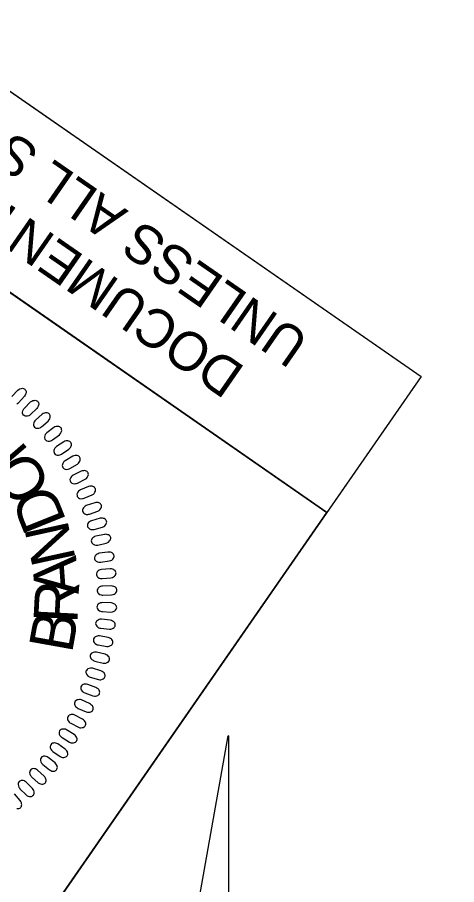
# Model space of a CAD drawing. Extents: x 478372 to 480379, y 492840 to 494699.
# Drawn here: x 478604.8 to 478667.1, y 493764.6 to 493887.7 of the extents above; entities that cross this region are included whole.
import ezdxf

# ---------------------------------------------------------------- set-up
doc = ezdxf.new("R2010")
doc.units = 0
for name, color, linetype in [('Prop North Arrow NAD83 for Plan Sheets CELL', 7, 'Continuous'), ('Sheet Clip Boundary CELL', 7, 'Continuous'), ('Sheet PE Seal Cell', 7, 'Continuous'), ('Sheet Plan CELL', 7, 'Continuous'), ('Sheet Sticker Exception Certification CELL', 7, 'Continuous')]:
    doc.layers.add(name, color=color, linetype=linetype)

msp = doc.modelspace()

# ---------------------------------------------------------------- linework, layer by layer
at = {"layer": 'Prop North Arrow NAD83 for Plan Sheets CELL'}
for p, q in [((478626.5, 493739.35), (478634.7, 493785.7)), ((478634.75, 493785.7), (478634.7, 493785.7)), ((478634.75, 493785.7), (478634.7, 493785.7)), ((478634.75, 493785.7), (478634.75, 493737.9))]:
    msp.add_line(p, q, dxfattribs=at)
at = {"layer": 'Sheet Clip Boundary CELL'}
msp.add_lwpolyline([(479740.65, 493110.71), (479819.09, 493331.13), (479938.9, 493670.6), (480035.01, 493951.06), (479137.46, 494573.68), (479091.85, 494507.93), (479078.63, 494420.53), (478968.98, 494336.48), (478682.91, 494117.93), (478570.32, 494055.33), (478497.76, 493950.74), (478662.13, 493836.73), (478563.21, 493694.11), (479631.38, 492953.18)], close=True, dxfattribs=at)
at = {"layer": 'Sheet PE Seal Cell'}
for points in [[(478604.04, 493833.87), (478604.87, 493834.78), (478605.04, 493834.92), (478605.17, 493834.99), (478605.37, 493835.04), (478605.51, 493835.06), (478605.65, 493835.04), (478605.76, 493835), (478605.85, 493834.94), (478605.92, 493834.85), (478605.99, 493834.75), (478606.03, 493834.64), (478606.04, 493834.49), (478606.03, 493834.39), (478605.98, 493834.24), (478605.91, 493834.06), (478605.82, 493833.93), (478604.98, 493832.99), (478604.85, 493832.88), (478604.72, 493832.81)], [(478604.74, 493775.43), (478604.88, 493775.41), (478605.02, 493775.42), (478605.13, 493775.46), (478605.23, 493775.52), (478605.3, 493775.61), (478605.37, 493775.71), (478605.41, 493775.82), (478605.42, 493775.97), (478605.41, 493776.07), (478605.37, 493776.22), (478605.3, 493776.4), (478605.21, 493776.53), (478604.39, 493777.49)]]:
    msp.add_lwpolyline(points, dxfattribs=at)
for points in [[(478605.8, 493832.25), (478606.68, 493833.11), (478606.86, 493833.24), (478607, 493833.3), (478607.2, 493833.34), (478607.34, 493833.35), (478607.48, 493833.32), (478607.58, 493833.28), (478607.67, 493833.21), (478607.74, 493833.12), (478607.8, 493833.01), (478607.83, 493832.89), (478607.83, 493832.75), (478607.82, 493832.65), (478607.76, 493832.5), (478607.67, 493832.33), (478607.57, 493832.2), (478606.68, 493831.32), (478606.54, 493831.21), (478606.41, 493831.15), (478606.24, 493831.1), (478606.06, 493831.08), (478605.93, 493831.1), (478605.78, 493831.17), (478605.66, 493831.26), (478605.59, 493831.39), (478605.55, 493831.5), (478605.53, 493831.66), (478605.57, 493831.87), (478605.65, 493832.04), (478605.72, 493832.15)], [(478608.25, 493829.6), (478609.18, 493830.4), (478609.32, 493830.57), (478609.39, 493830.7), (478609.44, 493830.9), (478609.46, 493831.05), (478609.45, 493831.18), (478609.41, 493831.29), (478609.35, 493831.39), (478609.27, 493831.46), (478609.16, 493831.53), (478609.05, 493831.57), (478608.91, 493831.58), (478608.81, 493831.58), (478608.65, 493831.53), (478608.48, 493831.46), (478608.34, 493831.37), (478607.38, 493830.55), (478607.27, 493830.43), (478607.2, 493830.3), (478607.13, 493830.13), (478607.1, 493829.95), (478607.1, 493829.83), (478607.16, 493829.67), (478607.24, 493829.54), (478607.37, 493829.45), (478607.48, 493829.41), (478607.64, 493829.38), (478607.84, 493829.4), (478608.02, 493829.46), (478608.14, 493829.53)], [(478609.78, 493827.72), (478610.76, 493828.46), (478610.91, 493828.62), (478610.99, 493828.75), (478611.06, 493828.94), (478611.09, 493829.08), (478611.08, 493829.22), (478611.05, 493829.33), (478611, 493829.43), (478610.91, 493829.51), (478610.82, 493829.58), (478610.71, 493829.63), (478610.56, 493829.65), (478610.46, 493829.65), (478610.3, 493829.62), (478610.13, 493829.56), (478609.98, 493829.48), (478608.98, 493828.72), (478608.86, 493828.6), (478608.77, 493828.48), (478608.7, 493828.31), (478608.66, 493828.14), (478608.65, 493828.01), (478608.7, 493827.85), (478608.78, 493827.72), (478608.9, 493827.63), (478609, 493827.58), (478609.16, 493827.53), (478609.36, 493827.54), (478609.55, 493827.6), (478609.67, 493827.65)], [(478611.08, 493825.72), (478612.1, 493826.4), (478612.27, 493826.55), (478612.35, 493826.67), (478612.43, 493826.86), (478612.47, 493827), (478612.47, 493827.14), (478612.45, 493827.25), (478612.4, 493827.35), (478612.33, 493827.43), (478612.23, 493827.52), (478612.13, 493827.57), (478611.98, 493827.6), (478611.89, 493827.61), (478611.72, 493827.58), (478611.54, 493827.53), (478611.4, 493827.46), (478610.35, 493826.77), (478610.22, 493826.66), (478610.13, 493826.54), (478610.04, 493826.38), (478609.99, 493826.21), (478609.98, 493826.09), (478610.01, 493825.92), (478610.08, 493825.79), (478610.19, 493825.68), (478610.29, 493825.62), (478610.45, 493825.57), (478610.65, 493825.57), (478610.84, 493825.61), (478610.97, 493825.66)], [(478612.26, 493823.68), (478613.32, 493824.29), (478613.49, 493824.43), (478613.58, 493824.55), (478613.67, 493824.73), (478613.72, 493824.87), (478613.73, 493825.01), (478613.72, 493825.12), (478613.68, 493825.22), (478613.6, 493825.31), (478613.52, 493825.4), (478613.41, 493825.46), (478613.27, 493825.5), (478613.18, 493825.51), (478613.01, 493825.5), (478612.83, 493825.46), (478612.68, 493825.4), (478611.59, 493824.77), (478611.45, 493824.67), (478611.35, 493824.56), (478611.26, 493824.4), (478611.19, 493824.24), (478611.17, 493824.11), (478611.2, 493823.95), (478611.26, 493823.81), (478611.37, 493823.7), (478611.46, 493823.63), (478611.61, 493823.57), (478611.82, 493823.55), (478612.01, 493823.59), (478612.14, 493823.62)], [(478613.32, 493821.59), (478614.42, 493822.14), (478614.6, 493822.27), (478614.7, 493822.38), (478614.8, 493822.56), (478614.85, 493822.69), (478614.88, 493822.83), (478614.87, 493822.94), (478614.83, 493823.05), (478614.76, 493823.14), (478614.69, 493823.23), (478614.59, 493823.3), (478614.45, 493823.35), (478614.35, 493823.37), (478614.19, 493823.36), (478614, 493823.34), (478613.85, 493823.28), (478612.72, 493822.73), (478612.58, 493822.64), (478612.47, 493822.53), (478612.37, 493822.38), (478612.29, 493822.22), (478612.26, 493822.1), (478612.28, 493821.93), (478612.33, 493821.79), (478612.43, 493821.67), (478612.52, 493821.6), (478612.67, 493821.53), (478612.87, 493821.5), (478613.07, 493821.52), (478613.19, 493821.55)], [(478614.28, 493819.44), (478615.41, 493819.92), (478615.6, 493820.04), (478615.71, 493820.14), (478615.82, 493820.31), (478615.89, 493820.44), (478615.91, 493820.58), (478615.91, 493820.69), (478615.89, 493820.8), (478615.82, 493820.9), (478615.75, 493821), (478615.65, 493821.07), (478615.52, 493821.13), (478615.43, 493821.15), (478615.26, 493821.15), (478615.07, 493821.14), (478614.92, 493821.1), (478613.76, 493820.62), (478613.61, 493820.53), (478613.5, 493820.44), (478613.39, 493820.29), (478613.3, 493820.13), (478613.26, 493820.01), (478613.27, 493819.85), (478613.31, 493819.7), (478613.4, 493819.58), (478613.49, 493819.5), (478613.63, 493819.42), (478613.83, 493819.38), (478614.03, 493819.39), (478614.16, 493819.41)], [(478615.04, 493817.2), (478616.2, 493817.6), (478616.39, 493817.71), (478616.51, 493817.81), (478616.63, 493817.97), (478616.7, 493818.1), (478616.74, 493818.23), (478616.74, 493818.34), (478616.73, 493818.45), (478616.67, 493818.55), (478616.6, 493818.66), (478616.51, 493818.73), (478616.38, 493818.8), (478616.29, 493818.83), (478616.12, 493818.84), (478615.93, 493818.84), (478615.78, 493818.81), (478614.59, 493818.4), (478614.44, 493818.33), (478614.32, 493818.24), (478614.2, 493818.1), (478614.1, 493817.95), (478614.06, 493817.83), (478614.05, 493817.66), (478614.08, 493817.52), (478614.17, 493817.39), (478614.25, 493817.31), (478614.39, 493817.22), (478614.59, 493817.16), (478614.78, 493817.16), (478614.91, 493817.17)], [(478615.7, 493815.03), (478616.89, 493815.36), (478617.09, 493815.46), (478617.21, 493815.55), (478617.34, 493815.7), (478617.42, 493815.82), (478617.47, 493815.95), (478617.48, 493816.07), (478617.47, 493816.18), (478617.42, 493816.28), (478617.36, 493816.39), (478617.27, 493816.47), (478617.14, 493816.55), (478617.05, 493816.58), (478616.89, 493816.61), (478616.7, 493816.62), (478616.54, 493816.6), (478615.33, 493816.26), (478615.17, 493816.2), (478615.05, 493816.11), (478614.92, 493815.99), (478614.82, 493815.84), (478614.77, 493815.73), (478614.75, 493815.56), (478614.77, 493815.41), (478614.85, 493815.28), (478614.93, 493815.19), (478615.06, 493815.09), (478615.25, 493815.02), (478615.44, 493815.01), (478615.58, 493815.01)], [(478616.22, 493812.81), (478617.42, 493813.07), (478617.63, 493813.15), (478617.75, 493813.23), (478617.9, 493813.38), (478617.98, 493813.49), (478618.04, 493813.62), (478618.05, 493813.73), (478618.05, 493813.85), (478618.01, 493813.95), (478617.95, 493814.06), (478617.87, 493814.15), (478617.75, 493814.23), (478617.66, 493814.27), (478617.5, 493814.31), (478617.32, 493814.33), (478617.15, 493814.32), (478615.92, 493814.06), (478615.76, 493814.01), (478615.64, 493813.93), (478615.5, 493813.81), (478615.39, 493813.67), (478615.33, 493813.56), (478615.3, 493813.4), (478615.31, 493813.25), (478615.38, 493813.11), (478615.45, 493813.02), (478615.58, 493812.91), (478615.77, 493812.83), (478615.96, 493812.8), (478616.09, 493812.8)], [(478616.63, 493810.36), (478617.85, 493810.54), (478618.06, 493810.61), (478618.19, 493810.68), (478618.34, 493810.82), (478618.43, 493810.93), (478618.5, 493811.05), (478618.52, 493811.16), (478618.52, 493811.28), (478618.49, 493811.39), (478618.44, 493811.5), (478618.37, 493811.59), (478618.25, 493811.68), (478618.16, 493811.73), (478618.01, 493811.78), (478617.82, 493811.81), (478617.66, 493811.81), (478616.42, 493811.63), (478616.25, 493811.58), (478616.12, 493811.52), (478615.97, 493811.41), (478615.85, 493811.28), (478615.79, 493811.17), (478615.75, 493811), (478615.75, 493810.85), (478615.82, 493810.71), (478615.88, 493810.61), (478616, 493810.5), (478616.18, 493810.41), (478616.37, 493810.37), (478616.5, 493810.36)], [(478616.86, 493808.05), (478618.09, 493808.15), (478618.3, 493808.21), (478618.44, 493808.27), (478618.6, 493808.4), (478618.7, 493808.5), (478618.77, 493808.62), (478618.8, 493808.73), (478618.81, 493808.84), (478618.78, 493808.95), (478618.74, 493809.07), (478618.67, 493809.17), (478618.56, 493809.26), (478618.48, 493809.32), (478618.32, 493809.37), (478618.14, 493809.41), (478617.98, 493809.42), (478616.73, 493809.33), (478616.56, 493809.29), (478616.42, 493809.23), (478616.27, 493809.13), (478616.14, 493809.01), (478616.07, 493808.9), (478616.03, 493808.74), (478616.02, 493808.59), (478616.07, 493808.45), (478616.13, 493808.35), (478616.24, 493808.23), (478616.42, 493808.12), (478616.6, 493808.07), (478616.73, 493808.05)], [(478616.95, 493805.7), (478618.17, 493805.73), (478618.39, 493805.77), (478618.53, 493805.82), (478618.7, 493805.94), (478618.8, 493806.04), (478618.88, 493806.15), (478618.92, 493806.26), (478618.94, 493806.37), (478618.91, 493806.48), (478618.88, 493806.6), (478618.82, 493806.71), (478618.72, 493806.81), (478618.64, 493806.87), (478618.49, 493806.93), (478618.3, 493806.99), (478618.14, 493807.01), (478616.89, 493806.99), (478616.72, 493806.96), (478616.58, 493806.91), (478616.42, 493806.82), (478616.29, 493806.7), (478616.21, 493806.61), (478616.15, 493806.45), (478616.14, 493806.3), (478616.18, 493806.15), (478616.23, 493806.04), (478616.33, 493805.92), (478616.5, 493805.8), (478616.69, 493805.74), (478616.82, 493805.71)], [(478616.87, 493803.35), (478618.09, 493803.3), (478618.32, 493803.33), (478618.46, 493803.37), (478618.63, 493803.48), (478618.74, 493803.57), (478618.83, 493803.68), (478618.87, 493803.78), (478618.9, 493803.9), (478618.88, 493804.01), (478618.86, 493804.13), (478618.8, 493804.24), (478618.71, 493804.34), (478618.63, 493804.41), (478618.48, 493804.48), (478618.31, 493804.55), (478618.15, 493804.58), (478616.89, 493804.64), (478616.72, 493804.62), (478616.58, 493804.58), (478616.42, 493804.5), (478616.27, 493804.39), (478616.19, 493804.3), (478616.12, 493804.14), (478616.1, 493804), (478616.13, 493803.85), (478616.18, 493803.74), (478616.27, 493803.61), (478616.44, 493803.48), (478616.61, 493803.41), (478616.74, 493803.37)], [(478616.64, 493800.99), (478617.86, 493800.86), (478618.08, 493800.87), (478618.22, 493800.91), (478618.4, 493801.01), (478618.52, 493801.09), (478618.61, 493801.19), (478618.66, 493801.29), (478618.7, 493801.4), (478618.69, 493801.52), (478618.67, 493801.64), (478618.62, 493801.75), (478618.53, 493801.86), (478618.46, 493801.93), (478618.32, 493802.01), (478618.15, 493802.09), (478617.99, 493802.13), (478616.74, 493802.27), (478616.57, 493802.26), (478616.43, 493802.23), (478616.26, 493802.16), (478616.11, 493802.06), (478616.02, 493801.98), (478615.94, 493801.83), (478615.91, 493801.68), (478615.93, 493801.53), (478615.97, 493801.42), (478616.06, 493801.28), (478616.21, 493801.14), (478616.38, 493801.06), (478616.51, 493801.02)], [(478616.27, 493798.62), (478617.48, 493798.42), (478617.7, 493798.42), (478617.85, 493798.45), (478618.04, 493798.53), (478618.16, 493798.61), (478618.26, 493798.71), (478618.32, 493798.8), (478618.35, 493798.91), (478618.35, 493799.02), (478618.34, 493799.15), (478618.3, 493799.26), (478618.22, 493799.38), (478618.15, 493799.45), (478618.02, 493799.54), (478617.85, 493799.63), (478617.69, 493799.68), (478616.46, 493799.9), (478616.29, 493799.9), (478616.14, 493799.88), (478615.97, 493799.82), (478615.81, 493799.73), (478615.72, 493799.65), (478615.63, 493799.51), (478615.59, 493799.36), (478615.6, 493799.21), (478615.63, 493799.1), (478615.71, 493798.95), (478615.86, 493798.81), (478616.02, 493798.71), (478616.15, 493798.66)], [(478615.78, 493796.34), (478616.97, 493796.06), (478617.2, 493796.04), (478617.35, 493796.06), (478617.54, 493796.13), (478617.67, 493796.2), (478617.77, 493796.3), (478617.83, 493796.39), (478617.88, 493796.49), (478617.88, 493796.61), (478617.88, 493796.73), (478617.85, 493796.84), (478617.77, 493796.97), (478617.71, 493797.05), (478617.58, 493797.15), (478617.42, 493797.24), (478617.27, 493797.3), (478616.04, 493797.6), (478615.87, 493797.61), (478615.73, 493797.6), (478615.55, 493797.55), (478615.39, 493797.47), (478615.29, 493797.4), (478615.2, 493797.26), (478615.14, 493797.12), (478615.15, 493796.96), (478615.17, 493796.85), (478615.24, 493796.7), (478615.38, 493796.55), (478615.54, 493796.44), (478615.66, 493796.38)], [(478615.13, 493794.07), (478616.3, 493793.71), (478616.52, 493793.69), (478616.67, 493793.69), (478616.87, 493793.75), (478617, 493793.82), (478617.11, 493793.9), (478617.18, 493793.99), (478617.23, 493794.09), (478617.24, 493794.2), (478617.25, 493794.33), (478617.22, 493794.44), (478617.16, 493794.57), (478617.1, 493794.65), (478616.97, 493794.76), (478616.82, 493794.87), (478616.67, 493794.94), (478615.47, 493795.31), (478615.3, 493795.33), (478615.16, 493795.33), (478614.98, 493795.29), (478614.81, 493795.22), (478614.71, 493795.15), (478614.6, 493795.02), (478614.54, 493794.88), (478614.54, 493794.73), (478614.55, 493794.61), (478614.61, 493794.46), (478614.74, 493794.3), (478614.89, 493794.18), (478615.01, 493794.12)], [(478614.36, 493791.82), (478615.51, 493791.39), (478615.73, 493791.35), (478615.88, 493791.35), (478616.08, 493791.4), (478616.22, 493791.45), (478616.33, 493791.53), (478616.4, 493791.61), (478616.46, 493791.71), (478616.48, 493791.82), (478616.5, 493791.94), (478616.48, 493792.06), (478616.42, 493792.2), (478616.37, 493792.28), (478616.25, 493792.39), (478616.1, 493792.51), (478615.96, 493792.59), (478614.78, 493793.03), (478614.62, 493793.07), (478614.47, 493793.08), (478614.29, 493793.05), (478614.12, 493792.99), (478614.01, 493792.93), (478613.9, 493792.8), (478613.83, 493792.67), (478613.82, 493792.52), (478613.83, 493792.4), (478613.87, 493792.25), (478613.99, 493792.08), (478614.14, 493791.95), (478614.25, 493791.88)], [(478613.42, 493789.62), (478614.55, 493789.12), (478614.76, 493789.07), (478614.91, 493789.06), (478615.11, 493789.09), (478615.25, 493789.14), (478615.37, 493789.21), (478615.45, 493789.29), (478615.51, 493789.38), (478615.54, 493789.49), (478615.56, 493789.61), (478615.55, 493789.73), (478615.5, 493789.87), (478615.45, 493789.96), (478615.34, 493790.08), (478615.2, 493790.21), (478615.06, 493790.29), (478613.92, 493790.81), (478613.76, 493790.86), (478613.61, 493790.87), (478613.43, 493790.85), (478613.25, 493790.81), (478613.14, 493790.75), (478613.02, 493790.63), (478612.94, 493790.5), (478612.92, 493790.35), (478612.92, 493790.24), (478612.96, 493790.08), (478613.07, 493789.9), (478613.21, 493789.77), (478613.31, 493789.69)], [(478612.37, 493787.52), (478613.46, 493786.95), (478613.67, 493786.88), (478613.82, 493786.87), (478614.02, 493786.89), (478614.16, 493786.92), (478614.29, 493786.98), (478614.37, 493787.06), (478614.44, 493787.15), (478614.47, 493787.26), (478614.5, 493787.38), (478614.5, 493787.5), (478614.46, 493787.64), (478614.42, 493787.73), (478614.31, 493787.86), (478614.18, 493787.99), (478614.05, 493788.09), (478612.94, 493788.67), (478612.78, 493788.73), (478612.64, 493788.76), (478612.45, 493788.75), (478612.28, 493788.72), (478612.16, 493788.67), (478612.04, 493788.56), (478611.95, 493788.43), (478611.92, 493788.28), (478611.91, 493788.17), (478611.94, 493788.01), (478612.04, 493787.82), (478612.16, 493787.68), (478612.26, 493787.59)], [(478611.15, 493785.47), (478612.2, 493784.83), (478612.41, 493784.75), (478612.55, 493784.73), (478612.76, 493784.73), (478612.9, 493784.76), (478613.03, 493784.82), (478613.12, 493784.88), (478613.19, 493784.97), (478613.23, 493785.08), (478613.27, 493785.19), (478613.27, 493785.31), (478613.24, 493785.46), (478613.2, 493785.55), (478613.11, 493785.68), (478612.99, 493785.83), (478612.86, 493785.93), (478611.79, 493786.59), (478611.63, 493786.65), (478611.49, 493786.69), (478611.31, 493786.69), (478611.13, 493786.67), (478611.01, 493786.63), (478610.88, 493786.53), (478610.79, 493786.41), (478610.74, 493786.26), (478610.73, 493786.14), (478610.75, 493785.98), (478610.83, 493785.79), (478610.95, 493785.64), (478611.05, 493785.55)], [(478609.85, 493783.5), (478610.86, 493782.8), (478611.06, 493782.71), (478611.2, 493782.67), (478611.41, 493782.67), (478611.55, 493782.68), (478611.68, 493782.73), (478611.77, 493782.79), (478611.86, 493782.88), (478611.9, 493782.98), (478611.95, 493783.09), (478611.96, 493783.21), (478611.93, 493783.36), (478611.9, 493783.45), (478611.82, 493783.59), (478611.7, 493783.74), (478611.59, 493783.85), (478610.56, 493784.58), (478610.41, 493784.65), (478610.27, 493784.7), (478610.08, 493784.71), (478609.91, 493784.7), (478609.78, 493784.67), (478609.65, 493784.57), (478609.54, 493784.46), (478609.49, 493784.32), (478609.47, 493784.2), (478609.48, 493784.04), (478609.55, 493783.85), (478609.66, 493783.69), (478609.75, 493783.59)], [(478608.4, 493781.65), (478609.36, 493780.88), (478609.56, 493780.78), (478609.7, 493780.73), (478609.9, 493780.71), (478610.05, 493780.72), (478610.18, 493780.76), (478610.28, 493780.82), (478610.36, 493780.89), (478610.42, 493780.99), (478610.47, 493781.11), (478610.49, 493781.22), (478610.47, 493781.37), (478610.45, 493781.47), (478610.37, 493781.61), (478610.27, 493781.77), (478610.16, 493781.89), (478609.18, 493782.67), (478609.03, 493782.76), (478608.89, 493782.81), (478608.71, 493782.84), (478608.53, 493782.84), (478608.41, 493782.81), (478608.27, 493782.73), (478608.16, 493782.62), (478608.1, 493782.48), (478608.07, 493782.37), (478608.07, 493782.2), (478608.13, 493782.01), (478608.23, 493781.84), (478608.31, 493781.74)], [(478606.83, 493779.88), (478607.74, 493779.06), (478607.93, 493778.94), (478608.07, 493778.89), (478608.27, 493778.86), (478608.42, 493778.86), (478608.55, 493778.89), (478608.65, 493778.94), (478608.74, 493779.01), (478608.8, 493779.11), (478608.86, 493779.21), (478608.89, 493779.33), (478608.88, 493779.48), (478608.86, 493779.57), (478608.8, 493779.73), (478608.7, 493779.89), (478608.6, 493780.01), (478607.67, 493780.86), (478607.53, 493780.96), (478607.39, 493781.02), (478607.22, 493781.06), (478607.04, 493781.07), (478606.91, 493781.05), (478606.76, 493780.97), (478606.65, 493780.87), (478606.58, 493780.73), (478606.55, 493780.62), (478606.53, 493780.46), (478606.58, 493780.26), (478606.67, 493780.09), (478606.75, 493779.98)], [(478605.17, 493778.22), (478606.03, 493777.35), (478606.21, 493777.21), (478606.34, 493777.15), (478606.54, 493777.11), (478606.69, 493777.1), (478606.82, 493777.12), (478606.92, 493777.16), (478607.02, 493777.23), (478607.08, 493777.32), (478607.15, 493777.43), (478607.18, 493777.54), (478607.19, 493777.69), (478607.17, 493777.79), (478607.12, 493777.94), (478607.03, 493778.11), (478606.94, 493778.24), (478606.06, 493779.14), (478605.93, 493779.25), (478605.8, 493779.32), (478605.62, 493779.37), (478605.45, 493779.39), (478605.32, 493779.38), (478605.17, 493779.31), (478605.05, 493779.22), (478604.97, 493779.09), (478604.93, 493778.98), (478604.91, 493778.82), (478604.94, 493778.61), (478605.02, 493778.44), (478605.09, 493778.32)]]:
    msp.add_lwpolyline(points, close=True, dxfattribs=at)
at = {"layer": 'Sheet Plan CELL'}
for points in [[(480229.82, 493815.92), (479631.38, 492953.18), (478563.21, 493694.11), (478648.73, 493817.42), (478484.38, 493931.45), (478997.32, 494670.89)], [(478584.63, 493724.99), (478502.42, 493782.01), (478566.55, 493874.46), (478648.73, 493817.42)]]:
    msp.add_lwpolyline(points, close=True, dxfattribs=at)
at = {"layer": 'Sheet Sticker Exception Certification CELL'}
for p, q in [((478497.76, 493950.74), (478662.13, 493836.73)), ((478497.76, 493950.74), (478662.13, 493836.73)), ((478648.73, 493817.42), (478484.37, 493931.44)), ((478648.73, 493817.42), (478484.37, 493931.44)), ((478662.13, 493836.73), (478648.73, 493817.42)), ((478662.13, 493836.73), (478648.73, 493817.42))]:
    msp.add_line(p, q, dxfattribs=at)

# ---------------------------------------------------------------- texts
at = {"layer": 'Sheet PE Seal Cell'}
for s, rotation, p in [('N', 130.8021, (478606.56, 493826.21)), ('O', 120.7023, (478609.77, 493821.1)), ('D', 111.834, (478611.81, 493816.21)), ('N', 102.3443, (478613.13, 493810.69)), ('A', 94.2332, (478613.53, 493805.85)), ('R', 87.1163, (478613.31, 493801.6)), ('B', 79.8413, (478612.54, 493797.32))]:
    msp.add_text(s, height=6.24, rotation=rotation, dxfattribs=at).set_placement(p)
at = {"layer": 'Sheet Sticker Exception Certification CELL'}
for s, p in [('UNLESS ALL SIGNATURES COMPLETED', (478646.5, 493842.27)), ('UNLESS ALL SIGNATURES COMPLETED', (478646.5, 493842.27)), ('DOCUMENT NOT CONSIDERED FINAL', (478637.32, 493837.93)), ('DOCUMENT NOT CONSIDERED FINAL', (478637.32, 493837.93))]:
    msp.add_text(s, height=5.5, rotation=145.2516, dxfattribs=at).set_placement(p)

doc.saveas('drawing.dxf')
